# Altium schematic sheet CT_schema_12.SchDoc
size 502 x 385 mm
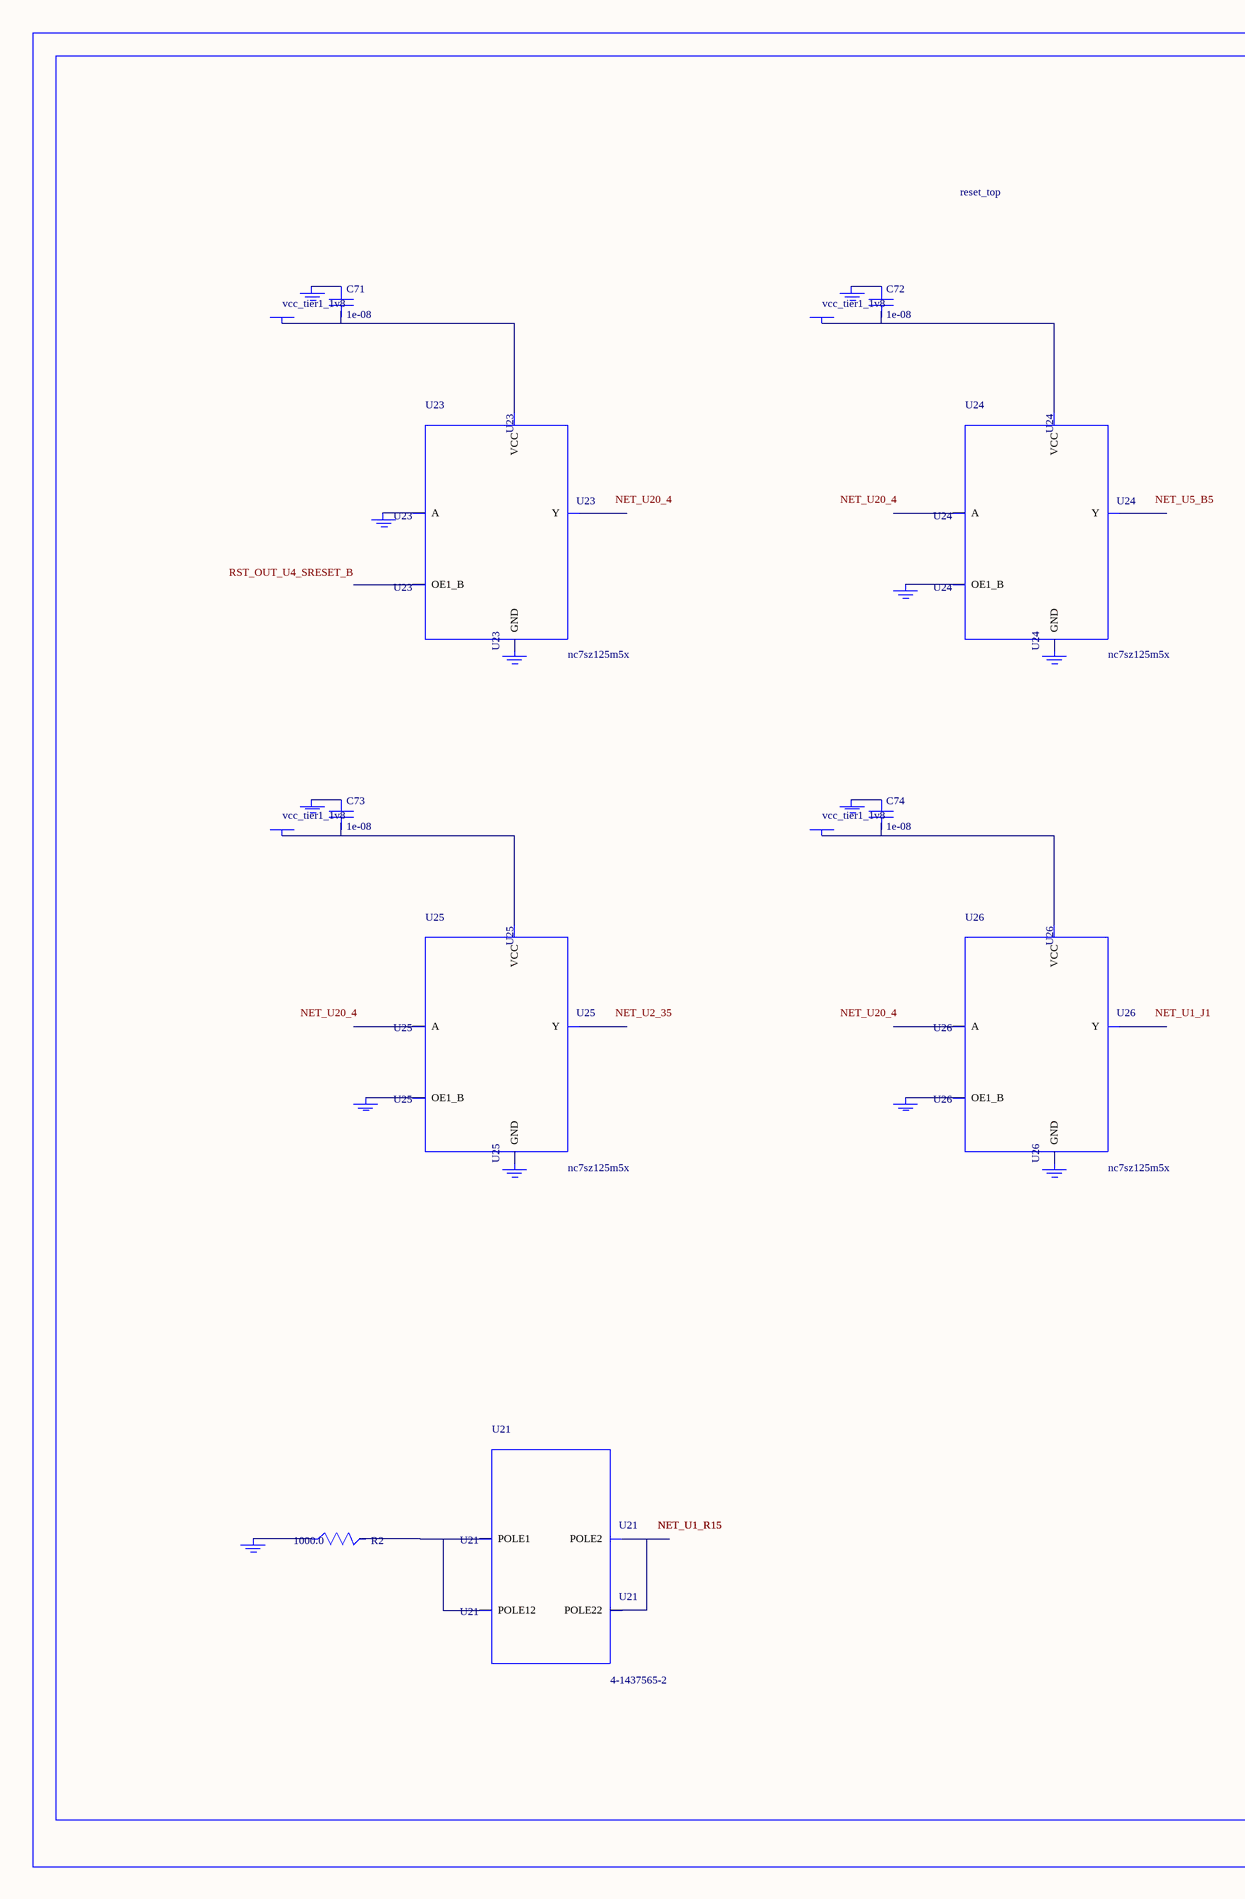
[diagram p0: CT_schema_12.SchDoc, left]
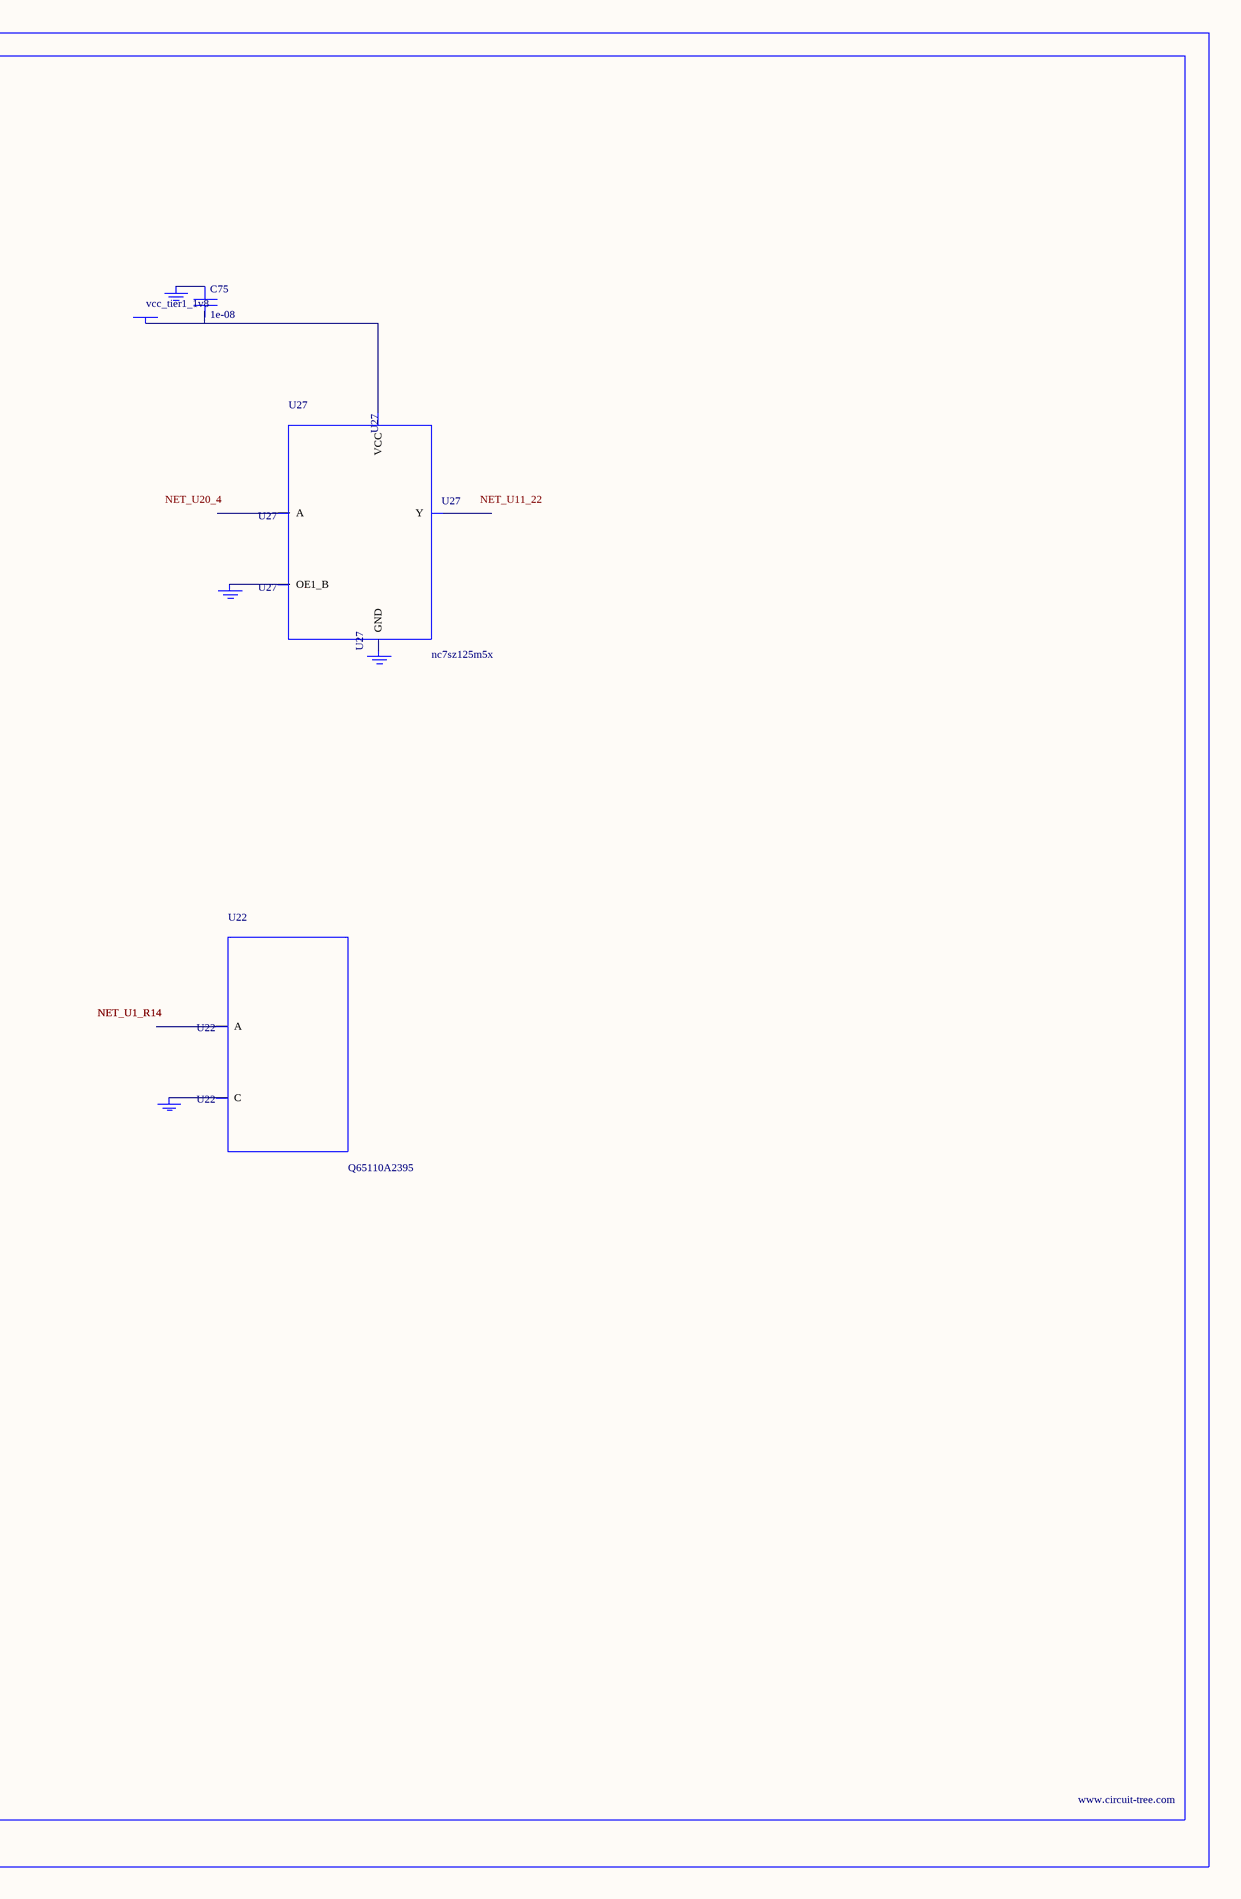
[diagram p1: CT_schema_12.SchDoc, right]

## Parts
BORDER11  (no value)
C71  1e-08  [C0402]
C72  1e-08  [C0402]
C73  1e-08  [C0402]
C74  1e-08  [C0402]
C75  1e-08  [C0402]
GND_INSTANCE_11_0  (no value)
GND_INSTANCE_11_1  (no value)
GND_INSTANCE_11_2  (no value)
GND_INSTANCE_11_3  (no value)
GND_INSTANCE_11_4  (no value)
GND_INSTANCE_11_5  (no value)
GND_INSTANCE_11_6  (no value)
GND_INSTANCE_11_7  (no value)
GND_INSTANCE_11_8  (no value)
GND_INSTANCE_11_9  (no value)
GND_INSTANCE_11_10  (no value)
GND_INSTANCE_11_11  (no value)
GND_INSTANCE_11_12  (no value)
GND_INSTANCE_11_13  (no value)
GND_INSTANCE_11_14  (no value)
GND_INSTANCE_11_15  (no value)
GND_INSTANCE_11_16  (no value)
POWER_INSTANCE_11_0  vcc_tier1_1v8
POWER_INSTANCE_11_1  vcc_tier1_1v8
POWER_INSTANCE_11_2  vcc_tier1_1v8
POWER_INSTANCE_11_3  vcc_tier1_1v8
POWER_INSTANCE_11_4  vcc_tier1_1v8
R2  1000.0  [R0603]
U21  4-1437565-2  [SW_4-1437565-2]
U22  Q65110A2395  [LGM67K-G1J2-24-Z]
U23  nc7sz125m5x  [NC7SZ125M5X]
U24  nc7sz125m5x  [NC7SZ125M5X]
U25  nc7sz125m5x  [NC7SZ125M5X]
U26  nc7sz125m5x  [NC7SZ125M5X]
U27  nc7sz125m5x  [NC7SZ125M5X]

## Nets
NetC71_1: C71.1 GND_INSTANCE_11_2.0(GND)
NetC71_2: C71.2 POWER_INSTANCE_11_0.0(PWR) U23.5(VCC)
NetC72_1: C72.1 GND_INSTANCE_11_5.0(GND)
NetC72_2: C72.2 POWER_INSTANCE_11_1.0(PWR) U24.5(VCC)
NetC73_1: C73.1 GND_INSTANCE_11_8.0(GND)
NetC73_2: C73.2 POWER_INSTANCE_11_2.0(PWR) U25.5(VCC)
NetC74_1: C74.1 GND_INSTANCE_11_11.0(GND)
NetC74_2: C74.2 POWER_INSTANCE_11_3.0(PWR) U26.5(VCC)
NetC75_1: C75.1 GND_INSTANCE_11_14.0(GND)
NetC75_2: C75.2 POWER_INSTANCE_11_4.0(PWR) U27.5(VCC)
NetGND_INSTANCE_11_0_0: GND_INSTANCE_11_0.0(GND) R2.1
NetGND_INSTANCE_11_1_0: GND_INSTANCE_11_1.0(GND) U22.C
NetGND_INSTANCE_11_3_0: GND_INSTANCE_11_3.0(GND) U23.2(A)
NetGND_INSTANCE_11_4_0: GND_INSTANCE_11_4.0(GND) U23.3(GND)
NetGND_INSTANCE_11_6_0: GND_INSTANCE_11_6.0(GND) U24.1(OE1_B)
NetGND_INSTANCE_11_7_0: GND_INSTANCE_11_7.0(GND) U24.3(GND)
NetGND_INSTANCE_11_9_0: GND_INSTANCE_11_9.0(GND) U25.1(OE1_B)
NetGND_INSTANCE_11_10_0: GND_INSTANCE_11_10.0(GND) U25.3(GND)
NetGND_INSTANCE_11_12_0: GND_INSTANCE_11_12.0(GND) U26.1(OE1_B)
NetGND_INSTANCE_11_13_0: GND_INSTANCE_11_13.0(GND) U26.3(GND)
NetGND_INSTANCE_11_15_0: GND_INSTANCE_11_15.0(GND) U27.1(OE1_B)
NetGND_INSTANCE_11_16_0: GND_INSTANCE_11_16.0(GND) U27.3(GND)
NetR2_2: R2.2 U21.1(POLE1) U21.2(POLE12)
NetU21_3: U21.3(POLE2) U21.4(POLE22)

Not connected (* = marked no-connect by the designer): U22 A; U23 1(OE1_B) 4(Y); U24 2(A) 4(Y); U25 2(A) 4(Y); U26 2(A) 4(Y); U27 2(A) 4(Y)

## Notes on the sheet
- Labels drawn without touching a wire or pin: NET_U1_J1, NET_U2_35, NET_U5_B5, NET_U11_22, NET_U20_4, RST_OUT_U4_SRESET_B

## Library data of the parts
BORDER11 = BORDER_PAGE11
C71-C75 = C0402C103K3RAC
GND_INSTANCE_11_0-GND_INSTANCE_11_16 = GND
POWER_INSTANCE_11_0-POWER_INSTANCE_11_4 = PWR
R2 = RC0603JR-071KL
